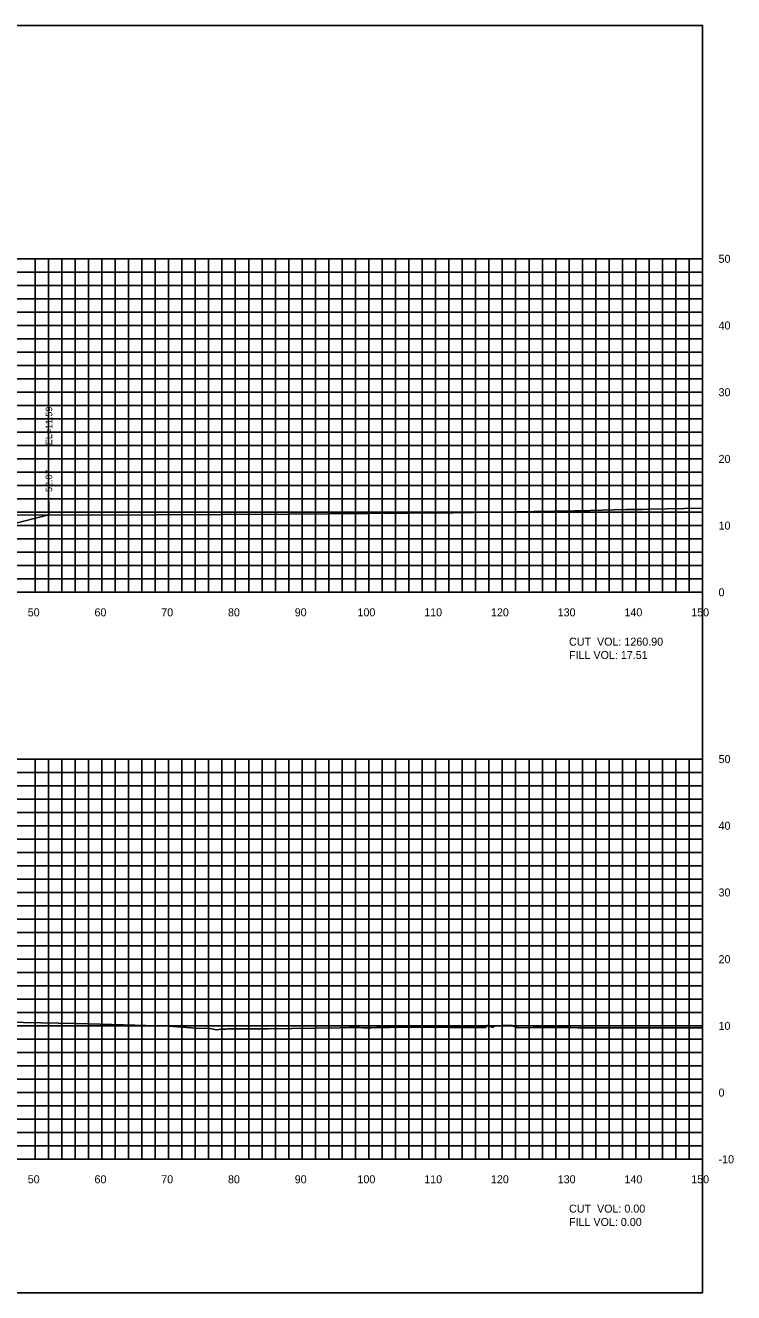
# Model space of a CAD drawing. Extents: x 1797305 to 1804485, y 245831 to 250849.
# Drawn here: x 1802339.5 to 1802445.7, y 250079.4 to 250269.4 of the extents above; entities that cross this region are included whole.
import ezdxf

# ---------------------------------------------------------------- set-up
doc = ezdxf.new("R2010")
doc.units = 0
for name, color, linetype in [('10', 7, 'Continuous'), ('29', 7, 'Continuous'), ('60', 7, 'Continuous'), ('CL-CNST', 7, 'Continuous'), ('EDPV-LINE', 7, 'Continuous'), ('Level 31', 7, 'Continuous'), ('LIMT-CSLINE', 7, 'Continuous'), ('M-ROADS', 7, 'Continuous')]:
    doc.layers.add(name, color=color, linetype=linetype)

msp = doc.modelspace()

# ---------------------------------------------------------------- linework, layer by layer
msp.add_line((1802343.07, 250196.03), (1802343.07, 250198.03))
msp.add_lwpolyline([(1802141, 250079.43), (1802441, 250079.43), (1802441, 250269.43), (1802141, 250269.43)], close=True)
at = {"layer": '29'}
for p, q in [((1802141, 250234.43), (1802441, 250234.43)), ((1802341, 250184.43), (1802341, 250234.43)), ((1802343, 250184.43), (1802343, 250234.43)), ((1802345, 250184.43), (1802345, 250234.43)), ((1802347, 250184.43), (1802347, 250234.43)), ((1802349, 250184.43), (1802349, 250234.43)), ((1802351, 250184.43), (1802351, 250234.43)), ((1802353, 250184.43), (1802353, 250234.43)), ((1802355, 250184.43), (1802355, 250234.43)), ((1802357, 250184.43), (1802357, 250234.43)), ((1802359, 250184.43), (1802359, 250234.43)), ((1802361, 250184.43), (1802361, 250234.43)), ((1802363, 250184.43), (1802363, 250234.43)), ((1802365, 250184.43), (1802365, 250234.43)), ((1802367, 250184.43), (1802367, 250234.43)), ((1802369, 250184.43), (1802369, 250234.43)), ((1802371, 250184.43), (1802371, 250234.43)), ((1802373, 250184.43), (1802373, 250234.43)), ((1802375, 250184.43), (1802375, 250234.43)), ((1802377, 250184.43), (1802377, 250234.43)), ((1802379, 250184.43), (1802379, 250234.43)), ((1802381, 250184.43), (1802381, 250234.43)), ((1802383, 250184.43), (1802383, 250234.43)), ((1802385, 250184.43), (1802385, 250234.43)), ((1802387, 250184.43), (1802387, 250234.43)), ((1802389, 250184.43), (1802389, 250234.43)), ((1802391, 250184.43), (1802391, 250234.43)), ((1802393, 250184.43), (1802393, 250234.43)), ((1802395, 250184.43), (1802395, 250234.43)), ((1802397, 250184.43), (1802397, 250234.43)), ((1802399, 250184.43), (1802399, 250234.43)), ((1802401, 250184.43), (1802401, 250234.43)), ((1802403, 250184.43), (1802403, 250234.43)), ((1802405, 250184.43), (1802405, 250234.43)), ((1802407, 250184.43), (1802407, 250234.43)), ((1802409, 250184.43), (1802409, 250234.43)), ((1802411, 250184.43), (1802411, 250234.43)), ((1802413, 250184.43), (1802413, 250234.43)), ((1802415, 250184.43), (1802415, 250234.43)), ((1802417, 250184.43), (1802417, 250234.43)), ((1802419, 250184.43), (1802419, 250234.43)), ((1802421, 250184.43), (1802421, 250234.43)), ((1802423, 250184.43), (1802423, 250234.43)), ((1802425, 250184.43), (1802425, 250234.43)), ((1802427, 250184.43), (1802427, 250234.43)), ((1802429, 250184.43), (1802429, 250234.43)), ((1802431, 250184.43), (1802431, 250234.43)), ((1802433, 250184.43), (1802433, 250234.43)), ((1802435, 250184.43), (1802435, 250234.43)), ((1802437, 250184.43), (1802437, 250234.43)), ((1802439, 250184.43), (1802439, 250234.43)), ((1802441, 250184.43), (1802441, 250234.43)), ((1802141, 250232.43), (1802441, 250232.43)), ((1802141, 250230.43), (1802441, 250230.43)), ((1802141, 250228.43), (1802441, 250228.43)), ((1802141, 250226.43), (1802441, 250226.43)), ((1802141, 250224.43), (1802441, 250224.43)), ((1802141, 250222.43), (1802441, 250222.43)), ((1802141, 250220.43), (1802441, 250220.43)), ((1802141, 250218.43), (1802441, 250218.43)), ((1802141, 250216.43), (1802441, 250216.43)), ((1802141, 250214.43), (1802441, 250214.43)), ((1802141, 250212.43), (1802441, 250212.43)), ((1802141, 250210.43), (1802441, 250210.43)), ((1802141, 250208.43), (1802441, 250208.43)), ((1802141, 250206.43), (1802441, 250206.43)), ((1802141, 250204.43), (1802441, 250204.43)), ((1802141, 250202.43), (1802441, 250202.43)), ((1802141, 250200.43), (1802441, 250200.43)), ((1802141, 250198.43), (1802441, 250198.43)), ((1802141, 250196.43), (1802441, 250196.43)), ((1802141, 250194.43), (1802441, 250194.43)), ((1802141, 250192.43), (1802441, 250192.43)), ((1802141, 250190.43), (1802441, 250190.43)), ((1802141, 250188.43), (1802441, 250188.43)), ((1802141, 250186.43), (1802441, 250186.43)), ((1802141, 250184.43), (1802441, 250184.43)), ((1802141, 250159.43), (1802441, 250159.43)), ((1802341, 250099.43), (1802341, 250159.43)), ((1802343, 250099.43), (1802343, 250159.43)), ((1802345, 250099.43), (1802345, 250159.43)), ((1802347, 250099.43), (1802347, 250159.43)), ((1802349, 250099.43), (1802349, 250159.43)), ((1802351, 250099.43), (1802351, 250159.43)), ((1802353, 250099.43), (1802353, 250159.43)), ((1802355, 250099.43), (1802355, 250159.43)), ((1802357, 250099.43), (1802357, 250159.43)), ((1802359, 250099.43), (1802359, 250159.43)), ((1802361, 250099.43), (1802361, 250159.43)), ((1802363, 250099.43), (1802363, 250159.43)), ((1802365, 250099.43), (1802365, 250159.43)), ((1802367, 250099.43), (1802367, 250159.43)), ((1802369, 250099.43), (1802369, 250159.43)), ((1802371, 250099.43), (1802371, 250159.43)), ((1802373, 250099.43), (1802373, 250159.43)), ((1802375, 250099.43), (1802375, 250159.43)), ((1802377, 250099.43), (1802377, 250159.43)), ((1802379, 250099.43), (1802379, 250159.43)), ((1802381, 250099.43), (1802381, 250159.43)), ((1802383, 250099.43), (1802383, 250159.43)), ((1802385, 250099.43), (1802385, 250159.43)), ((1802387, 250099.43), (1802387, 250159.43)), ((1802389, 250099.43), (1802389, 250159.43)), ((1802391, 250099.43), (1802391, 250159.43)), ((1802393, 250099.43), (1802393, 250159.43)), ((1802395, 250099.43), (1802395, 250159.43)), ((1802397, 250099.43), (1802397, 250159.43)), ((1802399, 250099.43), (1802399, 250159.43)), ((1802401, 250099.43), (1802401, 250159.43)), ((1802403, 250099.43), (1802403, 250159.43)), ((1802405, 250099.43), (1802405, 250159.43)), ((1802407, 250099.43), (1802407, 250159.43)), ((1802409, 250099.43), (1802409, 250159.43)), ((1802411, 250099.43), (1802411, 250159.43)), ((1802413, 250099.43), (1802413, 250159.43)), ((1802415, 250099.43), (1802415, 250159.43)), ((1802417, 250099.43), (1802417, 250159.43)), ((1802419, 250099.43), (1802419, 250159.43)), ((1802421, 250099.43), (1802421, 250159.43)), ((1802423, 250099.43), (1802423, 250159.43)), ((1802425, 250099.43), (1802425, 250159.43)), ((1802427, 250099.43), (1802427, 250159.43)), ((1802429, 250099.43), (1802429, 250159.43)), ((1802431, 250099.43), (1802431, 250159.43)), ((1802433, 250099.43), (1802433, 250159.43)), ((1802435, 250099.43), (1802435, 250159.43)), ((1802437, 250099.43), (1802437, 250159.43)), ((1802439, 250099.43), (1802439, 250159.43)), ((1802441, 250099.43), (1802441, 250159.43)), ((1802141, 250157.43), (1802441, 250157.43)), ((1802141, 250155.43), (1802441, 250155.43)), ((1802141, 250153.43), (1802441, 250153.43)), ((1802141, 250151.43), (1802441, 250151.43)), ((1802141, 250149.43), (1802441, 250149.43)), ((1802141, 250147.43), (1802441, 250147.43)), ((1802141, 250145.43), (1802441, 250145.43)), ((1802141, 250143.43), (1802441, 250143.43)), ((1802141, 250141.43), (1802441, 250141.43)), ((1802141, 250139.43), (1802441, 250139.43)), ((1802141, 250137.43), (1802441, 250137.43)), ((1802141, 250135.43), (1802441, 250135.43)), ((1802141, 250133.43), (1802441, 250133.43)), ((1802141, 250131.43), (1802441, 250131.43)), ((1802141, 250129.43), (1802441, 250129.43)), ((1802141, 250127.43), (1802441, 250127.43)), ((1802141, 250125.43), (1802441, 250125.43)), ((1802141, 250123.43), (1802441, 250123.43)), ((1802141, 250121.43), (1802441, 250121.43)), ((1802141, 250119.43), (1802441, 250119.43)), ((1802141, 250117.43), (1802441, 250117.43)), ((1802141, 250115.43), (1802441, 250115.43)), ((1802141, 250113.43), (1802441, 250113.43)), ((1802141, 250111.43), (1802441, 250111.43)), ((1802141, 250109.43), (1802441, 250109.43)), ((1802141, 250107.43), (1802441, 250107.43)), ((1802141, 250105.43), (1802441, 250105.43)), ((1802141, 250103.43), (1802441, 250103.43)), ((1802141, 250101.43), (1802441, 250101.43)), ((1802141, 250099.43), (1802441, 250099.43))]:
    msp.add_line(p, q, dxfattribs=at)
at = {"layer": 'CL-CNST'}
msp.add_lwpolyline([(1802201.65, 250195.88), (1802236, 250192.45), (1802240, 250192.45), (1802261, 250195.95), (1802263, 250196.03), (1802267, 250196.19), (1802291, 250195.66), (1802299, 250195.34), (1802301, 250195.26), (1802322, 250191.76), (1802326, 250191.76), (1802343.07, 250196.03)], dxfattribs=at)
at = {"layer": 'Level 31'}
for p, q in [((1802441, 250184.43), (1802441, 250234.43)), ((1802441.06, 250234.43), (1802441, 250234.43)), ((1802441.06, 250224.43), (1802441, 250224.43)), ((1802441.06, 250214.43), (1802441, 250214.43)), ((1802441.06, 250204.43), (1802441, 250204.43)), ((1802441.06, 250194.43), (1802441, 250194.43)), ((1802141, 250184.43), (1802441, 250184.43)), ((1802341, 250184.37), (1802341, 250184.43)), ((1802351, 250184.37), (1802351, 250184.43)), ((1802361, 250184.37), (1802361, 250184.43)), ((1802371, 250184.37), (1802371, 250184.43)), ((1802381, 250184.37), (1802381, 250184.43)), ((1802391, 250184.37), (1802391, 250184.43)), ((1802401, 250184.37), (1802401, 250184.43)), ((1802411, 250184.37), (1802411, 250184.43)), ((1802421, 250184.37), (1802421, 250184.43)), ((1802431, 250184.37), (1802431, 250184.43)), ((1802441, 250184.37), (1802441, 250184.43)), ((1802441.06, 250184.43), (1802441, 250184.43)), ((1802441, 250099.43), (1802441, 250159.43)), ((1802441.06, 250159.43), (1802441, 250159.43)), ((1802441.06, 250149.43), (1802441, 250149.43)), ((1802441.06, 250139.43), (1802441, 250139.43)), ((1802441.06, 250129.43), (1802441, 250129.43)), ((1802441.06, 250119.43), (1802441, 250119.43)), ((1802441.06, 250109.43), (1802441, 250109.43)), ((1802141, 250099.43), (1802441, 250099.43)), ((1802341, 250099.37), (1802341, 250099.43)), ((1802351, 250099.37), (1802351, 250099.43)), ((1802361, 250099.37), (1802361, 250099.43)), ((1802371, 250099.37), (1802371, 250099.43)), ((1802381, 250099.37), (1802381, 250099.43)), ((1802391, 250099.37), (1802391, 250099.43)), ((1802401, 250099.37), (1802401, 250099.43)), ((1802411, 250099.37), (1802411, 250099.43)), ((1802421, 250099.37), (1802421, 250099.43)), ((1802431, 250099.37), (1802431, 250099.43)), ((1802441, 250099.37), (1802441, 250099.43)), ((1802441.06, 250099.43), (1802441, 250099.43))]:
    msp.add_line(p, q, dxfattribs=at)
at = {"layer": 'M-ROADS'}
for points in [[(1802334.54, 250195.97), (1802339.57, 250196.03), (1802349.41, 250196.01), (1802378.99, 250196.15), (1802402.94, 250196.35), (1802403.06, 250196.35), (1802403.15, 250196.35), (1802403.56, 250196.35), (1802403.63, 250196.35), (1802421.89, 250196.65), (1802422.02, 250196.65), (1802422.38, 250196.65), (1802429.58, 250196.83), (1802430.44, 250196.84), (1802430.93, 250196.84), (1802432.04, 250196.87), (1802432.86, 250196.88), (1802441, 250197.05)], [(1802333.99, 250120.02), (1802347.16, 250119.76), (1802352.57, 250119.65), (1802361.01, 250119.4), (1802364.39, 250119.11), (1802365.56, 250119.03), (1802366.91, 250119.07), (1802368.19, 250118.83), (1802368.19, 250118.83), (1802368.23, 250118.83), (1802368.84, 250118.93), (1802369.64, 250118.96), (1802369.82, 250118.97), (1802370.73, 250118.99), (1802370.95, 250118.99), (1802371.11, 250118.99), (1802375.8, 250119.01), (1802386.66, 250119.15), (1802386.98, 250119.16), (1802387.41, 250119.15), (1802388.05, 250119.16), (1802389.54, 250119.16), (1802390.09, 250119.15), (1802391.38, 250119.15), (1802391.78, 250119.16), (1802391.95, 250119.15), (1802392.13, 250119.16), (1802392.22, 250119.16), (1802393.71, 250119.18), (1802394.18, 250119.18), (1802400.67, 250119.22), (1802401.43, 250119.21), (1802402.92, 250119.19), (1802404.1, 250119.19), (1802404.55, 250119.2), (1802406.26, 250119.18), (1802406.47, 250119.18), (1802406.53, 250119.18), (1802407.35, 250119.18), (1802408.04, 250119.17), (1802408.5, 250119.17), (1802408.53, 250119.2), (1802408.59, 250119.3), (1802408.73, 250119.51), (1802408.73, 250119.51), (1802408.73, 250119.51), (1802408.73, 250119.51), (1802408.74, 250119.51), (1802408.76, 250119.5), (1802409.62, 250119.2), (1802409.81, 250119.38), (1802411.51, 250119.52), (1802412.36, 250119.49), (1802412.48, 250119.49), (1802413.17, 250119.18), (1802413.43, 250119.14), (1802415.64, 250119.18), (1802416.43, 250119.18), (1802416.47, 250119.18), (1802416.49, 250119.18), (1802418.03, 250119.17), (1802418.46, 250119.17), (1802419.63, 250119.16), (1802420.4, 250119.16), (1802421.25, 250119.16), (1802422.34, 250119.15), (1802422.89, 250119.14), (1802424.26, 250119.14), (1802424.55, 250119.14), (1802426.17, 250119.13), (1802426.22, 250119.13), (1802426.73, 250119.13), (1802427.73, 250119.13), (1802427.93, 250119.13), (1802428.29, 250119.13), (1802429.07, 250119.14), (1802429.63, 250119.14), (1802430.45, 250119.13), (1802430.51, 250119.13), (1802431.33, 250119.14), (1802431.83, 250119.14), (1802432.73, 250119.14), (1802433.03, 250119.13), (1802433.23, 250119.13), (1802434.03, 250119.14), (1802434.72, 250119.14), (1802434.8, 250119.14), (1802435.81, 250119.15), (1802436.46, 250119.14), (1802436.72, 250119.14), (1802437.58, 250119.15), (1802438.11, 250119.15), (1802438.75, 250119.15), (1802439.56, 250119.14), (1802440, 250119.15), (1802440.17, 250119.15), (1802440.8, 250119.14), (1802441, 250119.14)]]:
    msp.add_lwpolyline(points, dxfattribs=at)

# ---------------------------------------------------------------- texts
at = {"layer": '10'}
for s, p in [('50', (1802339.9, 250180.83)), ('60', (1802349.9, 250180.83)), ('70', (1802359.9, 250180.83)), ('80', (1802369.9, 250180.83)), ('90', (1802379.9, 250180.83)), ('100', (1802389.3, 250180.83)), ('110', (1802399.3, 250180.83)), ('120', (1802409.3, 250180.83)), ('130', (1802419.3, 250180.83)), ('140', (1802429.3, 250180.83)), ('150', (1802439.3, 250180.83)), ('50', (1802339.9, 250095.83)), ('60', (1802349.9, 250095.83)), ('70', (1802359.9, 250095.83)), ('80', (1802369.9, 250095.83)), ('90', (1802379.9, 250095.83)), ('100', (1802389.3, 250095.83)), ('110', (1802399.3, 250095.83)), ('120', (1802409.3, 250095.83)), ('130', (1802419.3, 250095.83)), ('140', (1802429.3, 250095.83)), ('150', (1802439.3, 250095.83))]:
    msp.add_text(s, height=1.2, dxfattribs=at).set_placement(p)
at = {"layer": '60'}
for s, p in [('50', (1802443.4, 250233.83)), ('40', (1802443.4, 250223.83)), ('30', (1802443.4, 250213.83)), ('20', (1802443.4, 250203.83)), ('10', (1802443.4, 250193.83)), ('0', (1802443.4, 250183.83)), ('50', (1802443.4, 250158.83)), ('40', (1802443.4, 250148.83)), ('30', (1802443.4, 250138.83)), ('20', (1802443.4, 250128.83)), ('10', (1802443.4, 250118.83)), ('0', (1802443.4, 250108.83)), ('-10', (1802443.4, 250098.83))]:
    msp.add_text(s, height=1.2, dxfattribs=at).set_placement(p)
at = {"layer": 'EDPV-LINE'}
for s, p in [('CUT  VOL: 1260.90', (1802421, 250176.43)), ('FILL VOL: 17.51', (1802421, 250174.43)), ('CUT  VOL: 0.00', (1802421, 250091.43)), ('FILL VOL: 0.00', (1802421, 250089.43))]:
    msp.add_text(s, height=1.2, dxfattribs=at).set_placement(p)
at = {"layer": 'LIMT-CSLINE'}
for s, p in [('EL=11.59', (1802343.57, 250206.5)), ('52.07', (1802343.57, 250199.47))]:
    msp.add_text(s, height=1, rotation=90, dxfattribs=at).set_placement(p)

doc.saveas('drawing.dxf')
